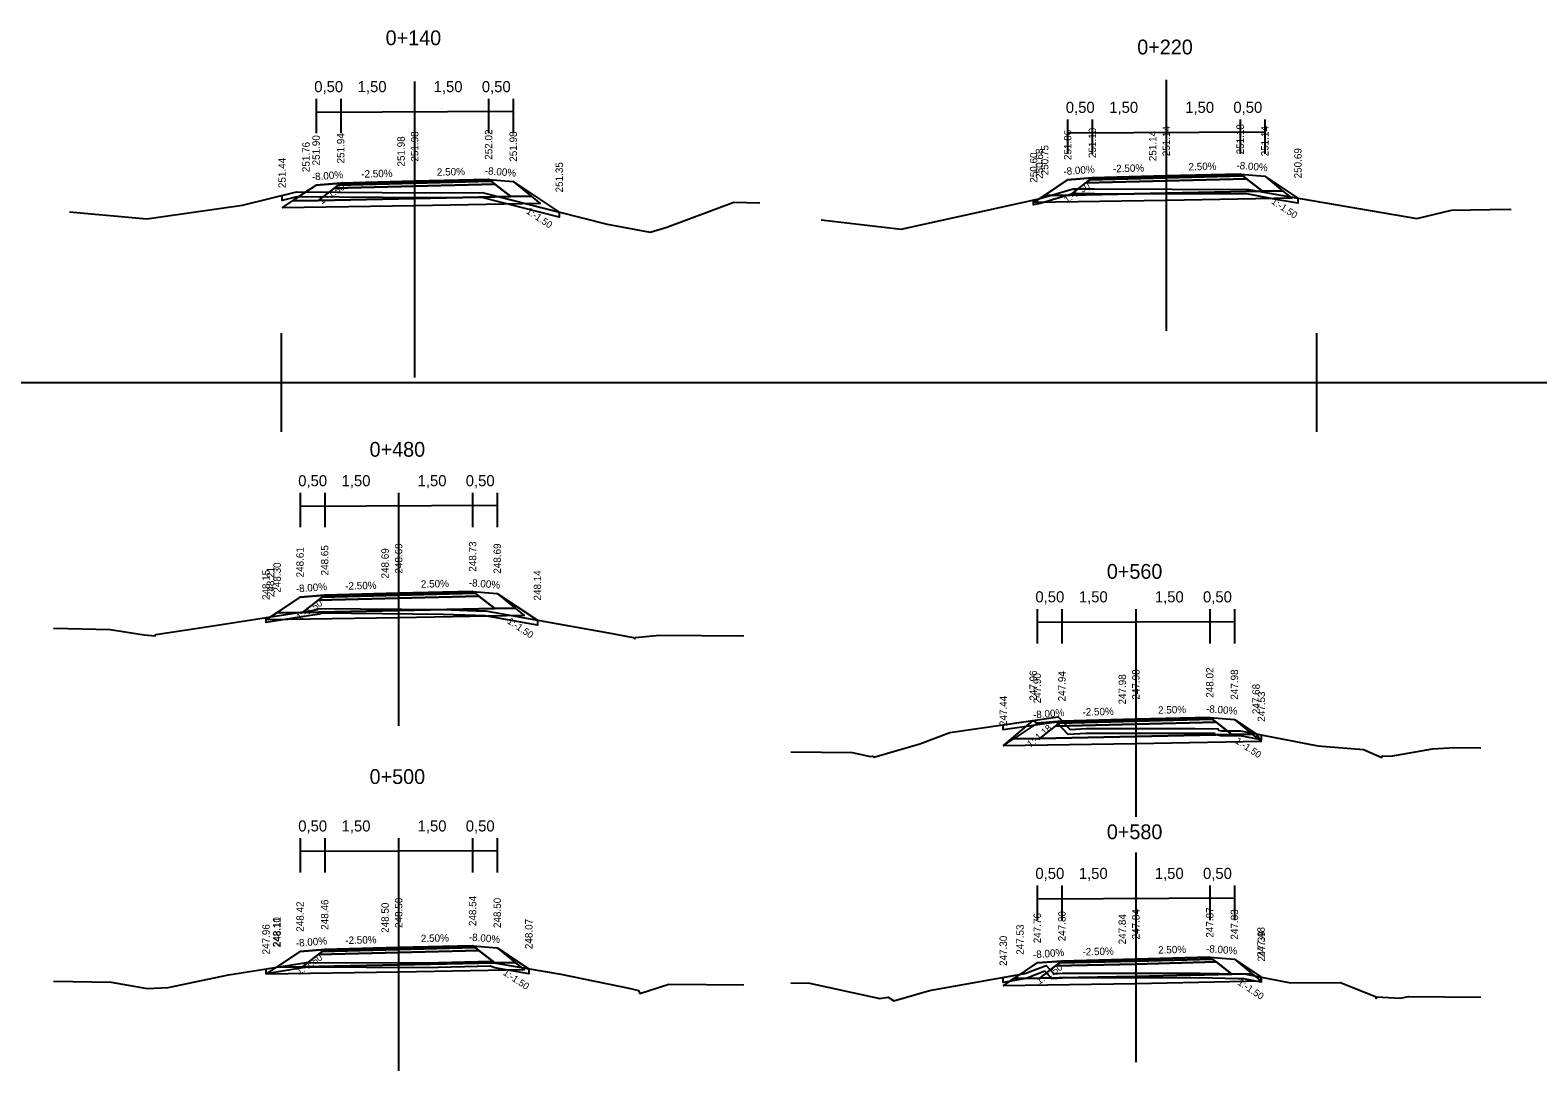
# Model space of a CAD drawing. Extents: x -552501 to -552394, y -1029983 to -1029892.
# Drawn here: x -552483.85 to -552453.26, y -1029937.02 to -1029915.9 of the extents above; entities that cross this region are included whole.
import ezdxf

# ---------------------------------------------------------------- set-up
doc = ezdxf.new("R2010")
doc.units = 0
for name, color, linetype in [('1', 7, 'Continuous'), ('16', 7, 'Continuous'), ('60', 7, 'Continuous'), ('9', 7, 'Continuous'), ('FORMATY', 7, 'Continuous'), ('Implicitní', 7, 'Continuous'), ('rámeček', 7, 'Continuous')]:
    doc.layers.add(name, color=color, linetype=linetype)

msp = doc.modelspace()

# ---------------------------------------------------------------- linework, layer by layer
for points in [[(-552478.74, -1029919.508), (-552478.255, -1029919.185), (-552478.05, -1029919.048), (-552477.55, -1029919.008), (-552476.05, -1029918.971), (-552474.55, -1029918.933), (-552474.05, -1029918.973), (-552473.117, -1029919.596)], [(-552463.493, -1029919.399), (-552463.376, -1029919.321), (-552463.268, -1029919.249), (-552462.803, -1029918.939), (-552462.303, -1029918.899), (-552460.803, -1029918.862), (-552459.303, -1029918.824), (-552458.803, -1029918.864), (-552458.132, -1029919.311)], [(-552483.05, -1029919.592), (-552481.482, -1029919.734), (-552479.54, -1029919.455), (-552478.45, -1029919.183), (-552475.834, -1029919.203), (-552474.678, -1029919.201), (-552472.145, -1029919.841), (-552471.271, -1029920.002), (-552470.932, -1029919.904), (-552469.573, -1029919.392), (-552469.05, -1029919.41)], [(-552467.803, -1029919.749), (-552466.183, -1029919.942), (-552463.385, -1029919.324), (-552462.693, -1029919.121), (-552462.258, -1029919.122), (-552459.124, -1029919.134), (-552458.52, -1029919.245), (-552455.72, -1029919.722), (-552455.014, -1029919.553), (-552453.844, -1029919.539), (-552453.803, -1029919.54)], [(-552479.065, -1029927.866), (-552478.974, -1029927.806), (-552478.84, -1029927.716), (-552478.375, -1029927.406), (-552477.875, -1029927.366), (-552476.375, -1029927.329), (-552474.875, -1029927.291), (-552474.375, -1029927.331), (-552473.56, -1029927.875)], [(-552483.375, -1029928.037), (-552482.228, -1029928.064), (-552481.538, -1029928.173), (-552481.316, -1029928.19), (-552481.302, -1029928.166), (-552480.274, -1029928.01), (-552478.361, -1029927.709), (-552478.017, -1029927.66), (-552477.986, -1029927.634), (-552475.47, -1029927.656), (-552474.81, -1029927.682), (-552474.612, -1029927.686), (-552472.117, -1029928.134), (-552471.62, -1029928.228), (-552471.58, -1029928.254), (-552471.576, -1029928.225), (-552471.083, -1029928.179), (-552469.375, -1029928.194)], [(-552468.42, -1029930.545), (-552467.173, -1029930.558), (-552466.805, -1029930.639), (-552466.763, -1029930.631), (-552466.733, -1029930.651), (-552465.804, -1029930.384), (-552465.196, -1029930.151), (-552462.993, -1029929.834), (-552462.749, -1029930.089), (-552462.429, -1029930.075), (-552460.224, -1029930.07), (-552459.758, -1029930.076), (-552459.742, -1029930.108), (-552459.69, -1029930.119), (-552459.294, -1029930.119), (-552457.725, -1029930.425), (-552456.8, -1029930.5), (-552456.426, -1029930.657), (-552456.424, -1029930.626), (-552456.25, -1029930.636), (-552455.398, -1029930.481), (-552454.951, -1029930.46), (-552454.42, -1029930.466)], [(-552464.11, -1029930.422), (-552463.502, -1029929.907), (-552463.42, -1029929.962), (-552462.92, -1029929.922), (-552461.42, -1029929.885), (-552459.92, -1029929.847), (-552459.42, -1029929.887), (-552458.981, -1029930.18), (-552458.874, -1029930.335)], [(-552463.42, -1029929.962), (-552463.502, -1029929.907)], [(-552479.065, -1029935.055), (-552478.851, -1029934.912), (-552478.84, -1029934.905), (-552478.375, -1029934.595), (-552477.875, -1029934.555), (-552476.375, -1029934.518), (-552474.875, -1029934.48), (-552474.375, -1029934.52), (-552473.734, -1029934.948)], [(-552483.375, -1029935.2), (-552482.208, -1029935.22), (-552481.479, -1029935.349), (-552481.048, -1029935.325), (-552479.828, -1029935.068), (-552478.247, -1029934.816), (-552475.838, -1029934.828), (-552474.491, -1029934.789), (-552474.395, -1029934.834), (-552473.085, -1029935.059), (-552471.668, -1029935.348), (-552471.512, -1029935.385), (-552471.485, -1029935.448), (-552470.896, -1029935.259), (-552469.375, -1029935.274)], [(-552464.11, -1029935.289), (-552463.769, -1029935.062), (-552463.42, -1029934.829), (-552462.92, -1029934.789), (-552461.42, -1029934.751), (-552459.92, -1029934.714), (-552459.42, -1029934.754), (-552458.881, -1029935.113), (-552458.874, -1029935.201)], [(-552468.42, -1029935.231), (-552468.039, -1029935.235), (-552466.611, -1029935.551), (-552466.447, -1029935.521), (-552466.328, -1029935.598), (-552465.606, -1029935.39), (-552463.673, -1029935.045), (-552463.242, -1029934.879), (-552463.083, -1029935.046), (-552462.912, -1029935.038), (-552460.131, -1029935.033), (-552459.347, -1029935.047), (-552459.219, -1029935.047), (-552458.284, -1029935.229), (-552457.267, -1029935.223), (-552456.546, -1029935.515), (-552456.543, -1029935.55), (-552456.54, -1029935.517), (-552456.053, -1029935.542), (-552455.889, -1029935.512), (-552454.42, -1029935.525)]]:
    msp.add_lwpolyline(points)
for points in [[(-552476.051, -1029919.011), (-552477.601, -1029919.048), (-552477.679, -1029919.108), (-552476.051, -1029919.071), (-552474.422, -1029919.027), (-552474.499, -1029918.967), (-552476.051, -1029919.011), (-552474.499, -1029918.967), (-552474.55, -1029918.933), (-552476.05, -1029918.971), (-552477.55, -1029919.008), (-552477.601, -1029919.048)], [(-552474.55, -1029918.933), (-552474.05, -1029918.973), (-552473.689, -1029919.271), (-552474.1, -1029919.277), (-552474.422, -1029919.027), (-552474.499, -1029918.967)], [(-552462.303, -1029918.899), (-552462.803, -1029918.939), (-552463.268, -1029919.249), (-552462.754, -1029919.249)], [(-552462.754, -1029919.249), (-552462.432, -1029918.999), (-552460.804, -1029918.962), (-552459.175, -1029918.918), (-552458.853, -1029919.168), (-552460.804, -1029919.212)], [(-552460.804, -1029918.902), (-552462.354, -1029918.939), (-552462.432, -1029918.999), (-552460.804, -1029918.962), (-552459.175, -1029918.918), (-552459.252, -1029918.858), (-552460.804, -1029918.902), (-552459.252, -1029918.858), (-552459.303, -1029918.824), (-552460.803, -1029918.862), (-552462.303, -1029918.899), (-552462.354, -1029918.939)], [(-552462.432, -1029918.999), (-552462.354, -1029918.939), (-552460.804, -1029918.902), (-552459.252, -1029918.858), (-552459.175, -1029918.918), (-552460.804, -1029918.962)], [(-552459.303, -1029918.824), (-552458.803, -1029918.864), (-552458.442, -1029919.162), (-552458.853, -1029919.168), (-552459.175, -1029918.918), (-552459.252, -1029918.858)], [(-552478.74, -1029919.256), (-552478.45, -1029919.183), (-552475.834, -1029919.203), (-552474.678, -1029919.201), (-552473.117, -1029919.596), (-552473.117, -1029919.699), (-552474.69, -1029919.301), (-552475.834, -1029919.303), (-552478.438, -1029919.283), (-552478.74, -1029919.359)], [(-552477.55, -1029919.008), (-552478.05, -1029919.048), (-552478.515, -1029919.358), (-552478.001, -1029919.358)], [(-552478.001, -1029919.358), (-552477.679, -1029919.108), (-552476.051, -1029919.071), (-552474.422, -1029919.027), (-552474.1, -1029919.277), (-552476.051, -1029919.321)], [(-552477.679, -1029919.108), (-552477.601, -1029919.048), (-552476.051, -1029919.011), (-552474.499, -1029918.967), (-552474.422, -1029919.027), (-552476.051, -1029919.071)], [(-552463.493, -1029919.348), (-552463.385, -1029919.324), (-552462.693, -1029919.121), (-552462.258, -1029919.122), (-552459.124, -1029919.134), (-552458.52, -1029919.245), (-552458.132, -1029919.311), (-552458.132, -1029919.413), (-552458.538, -1029919.344), (-552459.133, -1029919.234), (-552462.258, -1029919.222), (-552462.679, -1029919.221), (-552463.36, -1029919.421), (-552463.493, -1029919.45)], [(-552463.493, -1029919.399), (-552463.268, -1029919.249), (-552462.754, -1029919.249), (-552460.804, -1029919.212), (-552458.853, -1029919.168), (-552458.442, -1029919.162), (-552458.257, -1029919.312), (-552460.804, -1029919.362)], [(-552478.74, -1029919.508), (-552478.515, -1029919.358), (-552478.001, -1029919.358), (-552476.051, -1029919.321), (-552474.1, -1029919.277), (-552473.689, -1029919.271), (-552473.504, -1029919.421), (-552476.051, -1029919.471)], [(-552477.875, -1029927.366), (-552478.375, -1029927.406), (-552478.84, -1029927.716), (-552478.326, -1029927.716)], [(-552478.326, -1029927.716), (-552478.004, -1029927.466), (-552476.376, -1029927.429), (-552474.747, -1029927.385), (-552474.425, -1029927.635), (-552476.376, -1029927.679)], [(-552476.376, -1029927.369), (-552477.926, -1029927.406), (-552478.004, -1029927.466), (-552476.376, -1029927.429), (-552474.747, -1029927.385), (-552474.824, -1029927.325), (-552476.376, -1029927.369), (-552474.824, -1029927.325), (-552474.875, -1029927.291), (-552476.375, -1029927.329), (-552477.875, -1029927.366), (-552477.926, -1029927.406)], [(-552478.004, -1029927.466), (-552477.926, -1029927.406), (-552476.376, -1029927.369), (-552474.824, -1029927.325), (-552474.747, -1029927.385), (-552476.376, -1029927.429)], [(-552474.875, -1029927.291), (-552474.375, -1029927.331), (-552474.014, -1029927.629), (-552474.425, -1029927.635), (-552474.747, -1029927.385), (-552474.824, -1029927.325)], [(-552479.065, -1029927.866), (-552478.84, -1029927.716), (-552478.326, -1029927.716), (-552476.376, -1029927.679), (-552474.425, -1029927.635), (-552474.014, -1029927.629), (-552473.829, -1029927.779), (-552476.376, -1029927.829)], [(-552479.065, -1029927.82), (-552478.361, -1029927.709), (-552478.017, -1029927.66), (-552477.986, -1029927.634), (-552475.47, -1029927.656), (-552474.81, -1029927.682), (-552474.612, -1029927.686), (-552473.56, -1029927.875), (-552473.56, -1029927.977), (-552474.622, -1029927.786), (-552474.813, -1029927.782), (-552475.472, -1029927.756), (-552477.951, -1029927.735), (-552477.975, -1029927.755), (-552478.346, -1029927.808), (-552479.065, -1029927.921)], [(-552464.11, -1029929.995), (-552462.993, -1029929.834), (-552462.749, -1029930.089), (-552462.429, -1029930.075), (-552460.224, -1029930.07), (-552459.758, -1029930.076), (-552459.742, -1029930.108), (-552459.69, -1029930.119), (-552459.294, -1029930.119), (-552458.874, -1029930.201), (-552458.874, -1029930.302), (-552459.304, -1029930.219), (-552459.7, -1029930.219), (-552459.811, -1029930.196), (-552459.821, -1029930.175), (-552460.225, -1029930.17), (-552462.426, -1029930.175), (-552462.79, -1029930.191), (-552463.029, -1029929.94), (-552464.11, -1029930.096)], [(-552462.92, -1029929.922), (-552463.42, -1029929.962), (-552463.885, -1029930.272), (-552463.37, -1029930.272)], [(-552463.37, -1029930.272), (-552463.048, -1029930.022), (-552461.42, -1029929.985), (-552459.792, -1029929.941), (-552459.47, -1029930.191), (-552461.42, -1029930.235)], [(-552461.42, -1029929.925), (-552462.971, -1029929.962), (-552463.048, -1029930.022), (-552461.42, -1029929.985), (-552459.792, -1029929.941), (-552459.869, -1029929.881), (-552461.42, -1029929.925), (-552459.869, -1029929.881), (-552459.92, -1029929.847), (-552461.42, -1029929.885), (-552462.92, -1029929.922), (-552462.971, -1029929.962)], [(-552463.048, -1029930.022), (-552462.971, -1029929.962), (-552461.42, -1029929.925), (-552459.869, -1029929.881), (-552459.792, -1029929.941), (-552461.42, -1029929.985)], [(-552459.92, -1029929.847), (-552459.42, -1029929.887), (-552459.059, -1029930.185), (-552459.47, -1029930.191), (-552459.792, -1029929.941), (-552459.869, -1029929.881)], [(-552464.11, -1029930.422), (-552463.885, -1029930.272), (-552463.37, -1029930.272), (-552461.42, -1029930.235), (-552459.47, -1029930.191), (-552459.059, -1029930.185), (-552458.874, -1029930.335), (-552461.42, -1029930.385)], [(-552476.376, -1029934.558), (-552477.926, -1029934.595), (-552478.004, -1029934.655), (-552476.376, -1029934.618), (-552474.747, -1029934.574), (-552474.824, -1029934.514), (-552476.376, -1029934.558), (-552474.824, -1029934.514), (-552474.875, -1029934.48), (-552476.375, -1029934.518), (-552477.875, -1029934.555), (-552477.926, -1029934.595)], [(-552478.004, -1029934.655), (-552477.926, -1029934.595), (-552476.376, -1029934.558), (-552474.824, -1029934.514), (-552474.747, -1029934.574), (-552476.376, -1029934.618)], [(-552474.875, -1029934.48), (-552474.375, -1029934.52), (-552474.014, -1029934.818), (-552474.425, -1029934.824), (-552474.747, -1029934.574), (-552474.824, -1029934.514)], [(-552479.065, -1029934.946), (-552478.247, -1029934.816), (-552475.838, -1029934.828), (-552474.491, -1029934.789), (-552474.395, -1029934.834), (-552473.734, -1029934.948), (-552473.734, -1029935.049), (-552474.426, -1029934.93), (-552474.512, -1029934.89), (-552475.837, -1029934.928), (-552478.239, -1029934.916), (-552479.065, -1029935.048)], [(-552479.065, -1029935.055), (-552478.84, -1029934.905), (-552478.326, -1029934.905), (-552476.376, -1029934.868), (-552474.425, -1029934.824), (-552474.014, -1029934.818), (-552473.829, -1029934.968), (-552476.376, -1029935.018)], [(-552477.875, -1029934.555), (-552478.375, -1029934.595), (-552478.84, -1029934.905), (-552478.326, -1029934.905)], [(-552478.326, -1029934.905), (-552478.004, -1029934.655), (-552476.376, -1029934.618), (-552474.747, -1029934.574), (-552474.425, -1029934.824), (-552476.376, -1029934.868)], [(-552462.92, -1029934.789), (-552463.42, -1029934.829), (-552463.885, -1029935.139), (-552463.37, -1029935.139)], [(-552463.37, -1029935.139), (-552463.048, -1029934.889), (-552461.42, -1029934.851), (-552459.792, -1029934.808), (-552459.47, -1029935.058), (-552461.42, -1029935.101)], [(-552461.42, -1029934.791), (-552462.971, -1029934.829), (-552463.048, -1029934.889), (-552461.42, -1029934.851), (-552459.792, -1029934.808), (-552459.869, -1029934.748), (-552461.42, -1029934.791), (-552459.869, -1029934.748), (-552459.92, -1029934.714), (-552461.42, -1029934.751), (-552462.92, -1029934.789), (-552462.971, -1029934.829)], [(-552463.048, -1029934.889), (-552462.971, -1029934.829), (-552461.42, -1029934.791), (-552459.869, -1029934.748), (-552459.792, -1029934.808), (-552461.42, -1029934.851)], [(-552459.92, -1029934.714), (-552459.42, -1029934.754), (-552459.059, -1029935.051), (-552459.47, -1029935.058), (-552459.792, -1029934.808), (-552459.869, -1029934.748)], [(-552464.11, -1029935.123), (-552463.673, -1029935.045), (-552463.242, -1029934.879), (-552463.083, -1029935.046), (-552462.912, -1029935.038), (-552460.131, -1029935.033), (-552459.347, -1029935.047), (-552459.219, -1029935.047), (-552458.874, -1029935.114), (-552458.874, -1029935.216), (-552459.229, -1029935.147), (-552459.347, -1029935.147), (-552460.131, -1029935.133), (-552462.91, -1029935.138), (-552463.124, -1029935.147), (-552463.268, -1029934.997), (-552463.646, -1029935.141), (-552464.11, -1029935.224)], [(-552464.11, -1029935.289), (-552463.885, -1029935.139), (-552463.37, -1029935.139), (-552461.42, -1029935.101), (-552459.47, -1029935.058), (-552459.059, -1029935.051), (-552458.874, -1029935.201), (-552461.42, -1029935.251)]]:
    msp.add_lwpolyline(points, close=True)
at = {"layer": '60'}
for p, q in [((-552476.05, -1029916.949), (-552476.05, -1029922.949)), ((-552460.803, -1029916.915), (-552460.803, -1029922.003)), ((-552476.375, -1029926.017), (-552476.375, -1029930.017)), ((-552461.42, -1029927.864), (-552461.42, -1029931.864)), ((-552461.42, -1029932.589), (-552461.42, -1029936.841)), ((-552476.375, -1029933.017), (-552476.375, -1029937.017))]:
    msp.add_line(p, q, dxfattribs=at)
at = {"layer": '9'}
for p, q in [((-552478.05, -1029917.297), (-552478.05, -1029917.995)), ((-552477.55, -1029917.297), (-552477.55, -1029917.995)), ((-552476.05, -1029917.297), (-552476.05, -1029918.797)), ((-552474.55, -1029917.297), (-552474.55, -1029917.995)), ((-552474.05, -1029917.297), (-552474.05, -1029917.995)), ((-552462.803, -1029917.718), (-552462.803, -1029918.415)), ((-552462.303, -1029917.718), (-552462.303, -1029918.415)), ((-552460.803, -1029917.718), (-552460.803, -1029919.218)), ((-552459.303, -1029917.718), (-552459.303, -1029918.415)), ((-552458.803, -1029917.718), (-552458.803, -1029918.415)), ((-552478.375, -1029925.292), (-552478.375, -1029925.99)), ((-552477.875, -1029925.292), (-552477.875, -1029925.99)), ((-552476.375, -1029925.292), (-552476.375, -1029926.792)), ((-552474.875, -1029925.292), (-552474.875, -1029925.99)), ((-552474.375, -1029925.292), (-552474.375, -1029925.99)), ((-552463.42, -1029927.648), (-552463.42, -1029928.345)), ((-552462.92, -1029927.648), (-552462.92, -1029928.345)), ((-552461.42, -1029927.648), (-552461.42, -1029929.148)), ((-552459.92, -1029927.648), (-552459.92, -1029928.345)), ((-552459.42, -1029927.648), (-552459.42, -1029928.345)), ((-552478.375, -1029932.296), (-552478.375, -1029932.993)), ((-552477.875, -1029932.296), (-552477.875, -1029932.993)), ((-552476.375, -1029932.296), (-552476.375, -1029933.796)), ((-552474.875, -1029932.296), (-552474.875, -1029932.993)), ((-552474.375, -1029932.296), (-552474.375, -1029932.993)), ((-552463.42, -1029933.259), (-552463.42, -1029933.957)), ((-552462.92, -1029933.259), (-552462.92, -1029933.957)), ((-552461.42, -1029933.259), (-552461.42, -1029934.759)), ((-552459.92, -1029933.259), (-552459.92, -1029933.957)), ((-552459.42, -1029933.259), (-552459.42, -1029933.957))]:
    msp.add_line(p, q, dxfattribs=at)
at = {"layer": 'FORMATY'}
for p, q in [((-552478.755, -1029922.05), (-552478.755, -1029924.05)), ((-552457.755, -1029922.05), (-552457.755, -1029924.05)), ((-552479.755, -1029923.05), (-552477.755, -1029923.05)), ((-552458.755, -1029923.05), (-552456.755, -1029923.05))]:
    msp.add_line(p, q, dxfattribs=at)
at = {"layer": 'Implicitní'}
for p, q in [((-552478.04, -1029917.565), (-552474.05, -1029917.547)), ((-552462.793, -1029917.985), (-552458.803, -1029917.968)), ((-552478.365, -1029925.56), (-552474.375, -1029925.542)), ((-552463.41, -1029927.915), (-552459.42, -1029927.898)), ((-552478.365, -1029932.563), (-552474.375, -1029932.546)), ((-552463.41, -1029933.527), (-552459.42, -1029933.509))]:
    msp.add_line(p, q, dxfattribs=at)
at = {"layer": 'rámeček'}
for p, q in [((-552478.755, -1029922.55), (-552478.755, -1029923.05)), ((-552457.755, -1029922.55), (-552457.755, -1029923.05)), ((-552499.755, -1029923.05), (-552394.755, -1029923.05)), ((-552499.755, -1029923.05), (-552394.755, -1029923.05)), ((-552499.755, -1029923.05), (-552394.755, -1029923.05))]:
    msp.add_line(p, q, dxfattribs=at)

# ---------------------------------------------------------------- texts
for s, rotation, p in [('1:-1.50', 33.6902, (-552477.936, -1029919.441)), ('1:-1.50', 33.6902, (-552462.819, -1029919.419)), ('1:-1.50', 326.3098, (-552473.8, -1029919.609)), ('1:-1.50', 326.3098, (-552458.684, -1029919.412)), ('1:-1.50', 33.6902, (-552478.391, -1029927.886)), ('1:-1.50', 326.3098, (-552474.184, -1029927.928)), ('1:-1.18', 40.2571, (-552463.554, -1029930.462)), ('1:-1.50', 326.3098, (-552459.417, -1029930.358)), ('1:-1.50', 33.6902, (-552478.391, -1029935.075)), ('1:-1.50', 33.6902, (-552463.378, -1029935.27)), ('1:-1.50', 326.3098, (-552474.271, -1029935.058)), ('1:-1.50', 326.3098, (-552459.367, -1029935.258))]:
    msp.add_text(s, height=0.14, rotation=rotation).set_placement(p)
at = {"layer": '1'}
for s, p in [('0+140', (-552476.639, -1029916.209)), ('0+220', (-552461.391, -1029916.396)), ('0+480', (-552476.964, -1029924.558)), ('0+560', (-552462.008, -1029927.034)), ('0+500', (-552476.964, -1029931.197)), ('0+580', (-552462.008, -1029932.317))]:
    msp.add_text(s, height=0.3, dxfattribs=at).set_placement(p)
at = {"layer": '16'}
for s, p in [('0,50', (-552478.087, -1029917.162)), ('1,50', (-552477.206, -1029917.162)), ('1,50', (-552475.665, -1029917.162)), ('0,50', (-552474.687, -1029917.162)), ('0,50', (-552462.84, -1029917.583)), ('1,50', (-552461.959, -1029917.583)), ('1,50', (-552460.418, -1029917.583)), ('0,50', (-552459.441, -1029917.583)), ('0,50', (-552478.412, -1029925.157)), ('1,50', (-552477.532, -1029925.157)), ('1,50', (-552475.99, -1029925.157)), ('0,50', (-552475.013, -1029925.157)), ('0,50', (-552463.457, -1029927.513)), ('1,50', (-552462.576, -1029927.513)), ('1,50', (-552461.034, -1029927.513)), ('0,50', (-552460.057, -1029927.513)), ('0,50', (-552478.412, -1029932.161)), ('1,50', (-552477.532, -1029932.161)), ('1,50', (-552475.99, -1029932.161)), ('0,50', (-552475.013, -1029932.161)), ('0,50', (-552463.457, -1029933.124)), ('1,50', (-552462.576, -1029933.124)), ('1,50', (-552461.034, -1029933.124)), ('0,50', (-552460.057, -1029933.124))]:
    msp.add_text(s, height=0.225, dxfattribs=at).set_placement(p)
for s, rotation, p in [('251.94', 90, (-552477.475, -1029918.608)), ('251.98', 90, (-552475.975, -1029918.571)), ('252.02', 90, (-552474.475, -1029918.533)), ('251.98', 90, (-552473.975, -1029918.573)), ('251.06', 90, (-552462.728, -1029918.539)), ('251.10', 90, (-552462.228, -1029918.499)), ('251.14', 90, (-552461.003, -1029918.562)), ('251.14', 90, (-552460.728, -1029918.462)), ('251.18', 90, (-552459.228, -1029918.424)), ('251.14', 90, (-552458.728, -1029918.464)), ('251.76', 90, (-552478.18, -1029918.785)), ('251.90', 90, (-552477.975, -1029918.648)), ('251.98', 90, (-552476.25, -1029918.671)), ('250.68', 90, (-552463.301, -1029918.921)), ('250.75', 90, (-552463.193, -1029918.849)), ('250.69', 90, (-552458.057, -1029918.911)), ('251.44', 90, (-552478.665, -1029919.108)), ('251.35', 90, (-552473.042, -1029919.196)), ('250.60', 90, (-552463.418, -1029918.999)), ('-2.50%', 1.4321, (-552461.885, -1029918.789)), ('2.50%', 1.4321, (-552460.35, -1029918.751)), ('-8.00%', 355.4261, (-552459.384, -1029918.718)), ('-8.00%', 4.5739, (-552478.131, -1029918.955)), ('-2.50%', 1.4321, (-552477.132, -1029918.898)), ('2.50%', 1.4321, (-552475.597, -1029918.859)), ('-8.00%', 355.4261, (-552474.631, -1029918.827)), ('-8.00%', 4.5739, (-552462.884, -1029918.846)), ('248.73', 90, (-552474.8, -1029926.891)), ('248.61', 90, (-552478.3, -1029927.006)), ('248.65', 90, (-552477.8, -1029926.966)), ('248.69', 90, (-552476.575, -1029927.029)), ('248.69', 90, (-552476.3, -1029926.929)), ('248.69', 90, (-552474.3, -1029926.931)), ('248.15', 90, (-552478.99, -1029927.466)), ('248.21', 90, (-552478.899, -1029927.406)), ('248.30', 90, (-552478.765, -1029927.316)), ('248.14', 90, (-552473.485, -1029927.475)), ('-8.00%', 4.5739, (-552478.456, -1029927.313)), ('-2.50%', 1.4321, (-552477.457, -1029927.256)), ('2.50%', 1.4321, (-552475.922, -1029927.217)), ('-8.00%', 355.4261, (-552474.956, -1029927.185)), ('247.96', 90, (-552463.427, -1029929.507)), ('247.90', 90, (-552463.345, -1029929.562)), ('247.94', 90, (-552462.845, -1029929.522)), ('247.98', 90, (-552461.62, -1029929.585)), ('247.98', 90, (-552461.345, -1029929.485)), ('248.02', 90, (-552459.845, -1029929.447)), ('247.98', 90, (-552459.345, -1029929.487)), ('247.68', 90, (-552458.906, -1029929.78)), ('247.53', 90, (-552458.799, -1029929.935)), ('247.44', 90, (-552464.035, -1029930.022)), ('-2.50%', 1.4321, (-552462.501, -1029929.812)), ('2.50%', 1.4321, (-552460.967, -1029929.773)), ('-8.00%', 355.4261, (-552460.001, -1029929.741)), ('-8.00%', 4.5739, (-552463.501, -1029929.869)), ('248.42', 90, (-552478.3, -1029934.195)), ('248.46', 90, (-552477.8, -1029934.155)), ('248.50', 90, (-552476.575, -1029934.218)), ('248.50', 90, (-552476.3, -1029934.118)), ('248.54', 90, (-552474.8, -1029934.08)), ('248.50', 90, (-552474.3, -1029934.12)), ('248.10', 90, (-552478.776, -1029934.512)), ('248.11', 90, (-552478.765, -1029934.505)), ('247.76', 90, (-552463.345, -1029934.429)), ('247.80', 90, (-552462.845, -1029934.389)), ('247.84', 90, (-552461.62, -1029934.451)), ('247.84', 90, (-552461.345, -1029934.351)), ('247.87', 90, (-552459.845, -1029934.314)), ('247.83', 90, (-552459.345, -1029934.354)), ('247.96', 90, (-552478.99, -1029934.655)), ('-8.00%', 355.4261, (-552474.956, -1029934.374)), ('248.07', 90, (-552473.659, -1029934.548)), ('247.53', 90, (-552463.694, -1029934.662)), ('247.48', 90, (-552458.806, -1029934.713)), ('247.39', 90, (-552458.799, -1029934.801)), ('-8.00%', 4.5739, (-552478.456, -1029934.501)), ('-2.50%', 1.4321, (-552477.457, -1029934.445)), ('2.50%', 1.4321, (-552475.922, -1029934.406)), ('247.30', 90, (-552464.035, -1029934.889)), ('-8.00%', 4.5739, (-552463.501, -1029934.735)), ('-2.50%', 1.4321, (-552462.501, -1029934.678)), ('2.50%', 1.4321, (-552460.967, -1029934.64)), ('-8.00%', 355.4261, (-552460.001, -1029934.607))]:
    msp.add_text(s, height=0.15, rotation=rotation, dxfattribs=at).set_placement(p)

doc.saveas('drawing.dxf')
